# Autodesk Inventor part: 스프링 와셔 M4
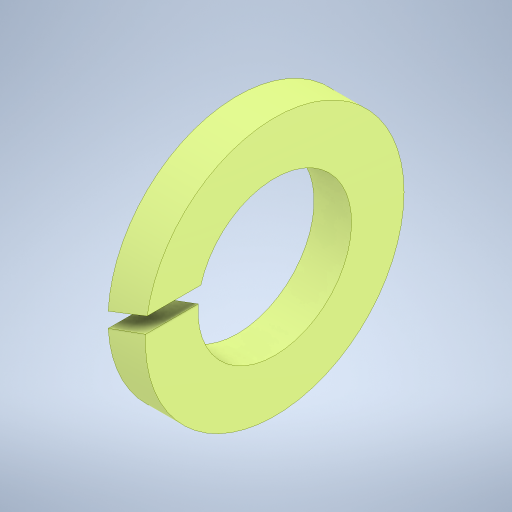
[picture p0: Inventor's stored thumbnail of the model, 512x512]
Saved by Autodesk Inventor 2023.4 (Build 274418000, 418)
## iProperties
Created: 2024-05
Part Number: 스프링 와셔 M4
Material: 강철, 연강
Description: 스프링 잠금 와셔
Document SubType Name: Modeling
Designer: user
Density: 7.85 g/cm^3
Appearance: 기본값
Author: jhkim
Sending System: Autodesk Inventor 2025
Preprocessor: ST-DEVELOPER v20
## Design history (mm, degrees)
feature "Solid1"
node "솔리드1"
